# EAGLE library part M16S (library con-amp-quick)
AMP QUICK CONNECTOR
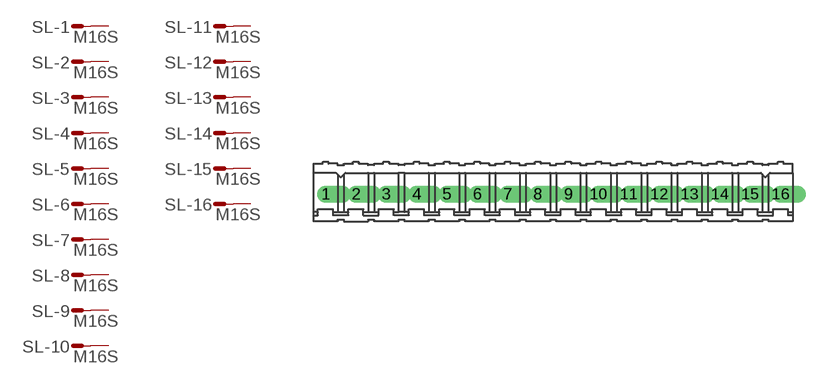
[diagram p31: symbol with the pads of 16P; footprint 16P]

Designator prefix SL; gates -1=M -2=M -3=M -4=M -5=M -6=M -7=M -8=M -9=M -10=M -11=M -12=M -13=M -14=M -15=M -16=M

## M16S  [16P]
1  -1:S  pas
2  -2:S  pas
3  -3:S  pas
4  -4:S  pas
5  -5:S  pas
6  -6:S  pas
7  -7:S  pas
8  -8:S  pas
9  -9:S  pas
10  -10:S  pas
11  -11:S  pas
12  -12:S  pas
13  -13:S  pas
14  -14:S  pas
15  -15:S  pas
16  -16:S  pas

## Footprint 16P (pad centres in mm)
AMP QUICK CONNECTOR
drill 0.914 offset: 1 -19.05,0; 2 -16.51,0; 3 -13.97,0; 4 -11.43,0; 5 -8.89,0; 6 -6.35,0; 7 -3.81,0; 8 -1.27,0; 9 1.27,0; 10 3.81,0; 11 6.35,0; 12 8.89,0; 13 11.43,0; 14 13.97,0; 15 16.51,0; 16 19.05,0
